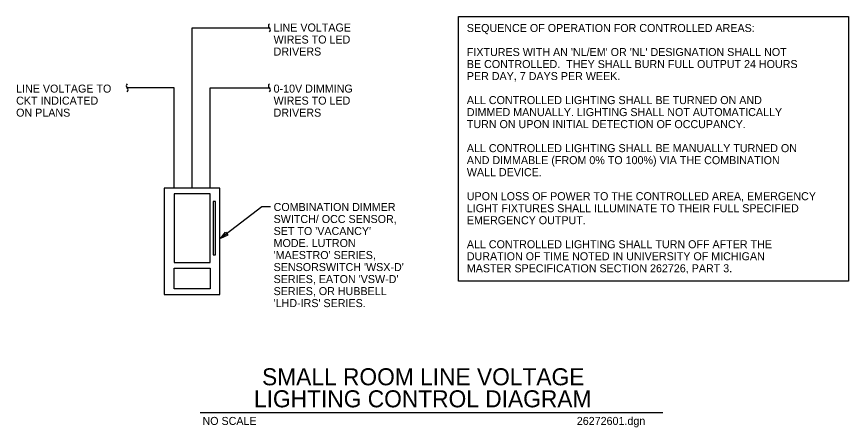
# Model space of a CAD drawing. Extents: x 10026.6 to 10095.9, y 10005.8 to 10040.
import ezdxf

# ---------------------------------------------------------------- set-up
doc = ezdxf.new("R2010")
doc.units = 0
for name, color, linetype in [('G-ANNO-CELL', 7, 'Continuous'), ('G-ANNO-TEXT', 7, 'Continuous'), ('G-DETL-LINE', 7, 'Continuous'), ('Level 3', 7, 'Continuous')]:
    doc.layers.add(name, color=color, linetype=linetype)

msp = doc.modelspace()

# ---------------------------------------------------------------- linework, layer by layer
at = {"layer": 'G-ANNO-CELL'}
msp.add_line((10041.898, 10007.023), (10080.422, 10007.023), dxfattribs=at)
at = {"layer": 'G-ANNO-TEXT'}
for points in [[(10063.404, 10039.974), (10095.865, 10039.974), (10095.865, 10017.948), (10063.404, 10017.948)], [(10044.202, 10021.776), (10043.574, 10021.497), (10043.997, 10022.039)]]:
    msp.add_lwpolyline(points, close=True, dxfattribs=at)
msp.add_lwpolyline([(10047.743, 10024.155), (10047.014, 10024.155), (10043.574, 10021.497)], dxfattribs=at)
at = {"layer": 'G-DETL-LINE'}
for p, q in [((10041.216, 10025.71), (10041.216, 10039.045)), ((10041.216, 10039.045), (10047.649, 10039.045)), ((10039.716, 10034.045), (10035.802, 10034.045)), ((10039.716, 10025.71), (10039.716, 10034.045)), ((10042.716, 10025.71), (10042.716, 10034.045)), ((10042.716, 10034.045), (10047.649, 10034.045))]:
    msp.add_line(p, q, dxfattribs=at)
for points in [[(10043.532, 10025.71), (10038.9, 10025.71), (10038.9, 10016.834), (10043.532, 10016.834)], [(10042.716, 10025.231), (10039.716, 10025.231), (10039.716, 10019.507), (10042.716, 10019.507)], [(10043.168, 10024.577), (10042.959, 10024.577), (10042.959, 10020.161), (10043.168, 10020.161)], [(10042.716, 10017.313), (10039.716, 10017.313), (10039.716, 10019.05), (10042.716, 10019.05)]]:
    msp.add_lwpolyline(points, close=True, dxfattribs=at)
for centre, start, end in [((10047.774, 10039.212), 126.8699, 233.1301), ((10047.524, 10038.879), 306.8699, 53.1301), ((10035.927, 10034.212), 126.8699, 233.1301), ((10047.774, 10034.212), 126.8699, 233.1301), ((10035.677, 10033.879), 306.8699, 53.1301), ((10047.524, 10033.879), 306.8699, 53.1301)]:
    msp.add_arc(centre, 0.208, start, end, dxfattribs=at)

# ---------------------------------------------------------------- texts
at = {"layer": 'G-ANNO-CELL'}
for s, height, p in [('SMALL ROOM LINE VOLTAGE', 1.41667, (10047.039, 10009.289)), ('LIGHTING CONTROL DIAGRAM', 1.41667, (10046.365, 10007.455)), ('NO SCALE', 0.6667, (10042.078, 10005.988))]:
    msp.add_text(s, height=height, dxfattribs=at).set_placement(p)
at = {"layer": 'G-ANNO-TEXT'}
for s, height, p in [('LINE VOLTAGE ', 0.66667, (10048.001, 10038.735)), ('SEQUENCE OF OPERATION FOR CONTROLLED AREAS:', 0.66667, (10064.092, 10038.695)), ('WIRES TO LED ', 0.66667, (10048.001, 10037.735)), ('DRIVERS', 0.6667, (10048.001, 10036.735)), ("FIXTURES WITH AN 'NL/EM' OR 'NL' DESIGNATION SHALL NOT ", 0.66667, (10064.092, 10036.695)), ('BE CONTROLLED.  THEY SHALL BURN FULL OUTPUT 24 HOURS ', 0.66667, (10064.092, 10035.695)), ('PER DAY, 7 DAYS PER WEEK.', 0.66667, (10064.092, 10034.695)), ('LINE VOLTAGE TO ', 0.66667, (10026.559, 10033.65)), ('0-10V DIMMING ', 0.66667, (10048.001, 10033.65)), ('CKT INDICATED ', 0.66667, (10026.559, 10032.65)), ('WIRES TO LED ', 0.66667, (10048.001, 10032.65)), ('ALL CONTROLLED LIGHTING SHALL BE TURNED ON AND ', 0.66667, (10064.092, 10032.695)), ('ON PLANS', 0.6667, (10026.559, 10031.65)), ('DRIVERS', 0.6667, (10048.001, 10031.65)), ('DIMMED MANUALLY. LIGHTING SHALL NOT AUTOMATICALLY ', 0.66667, (10064.092, 10031.695)), ('TURN ON UPON INITIAL DETECTION OF OCCUPANCY.', 0.66667, (10064.092, 10030.695)), ('ALL CONTROLLED LIGHTING SHALL BE MANUALLY TURNED ON ', 0.66667, (10064.092, 10028.695)), ('AND DIMMABLE (FROM 0% TO 100%) VIA THE COMBINATION ', 0.66667, (10064.092, 10027.695)), ('WALL DEVICE.', 0.66667, (10064.092, 10026.695)), ('UPON LOSS OF POWER TO THE CONTROLLED AREA, EMERGENCY ', 0.66667, (10064.092, 10024.695)), ('COMBINATION DIMMER ', 0.66667, (10048.001, 10023.796)), ('LIGHT FIXTURES SHALL ILLUMINATE TO THEIR FULL SPECIFIED ', 0.66667, (10064.092, 10023.695)), ('SWITCH/ OCC SENSOR, ', 0.66667, (10048.001, 10022.796)), ('EMERGENCY OUTPUT.', 0.66667, (10064.092, 10022.695)), ("SET TO 'VACANCY' ", 0.66667, (10048.001, 10021.796)), ('MODE. LUTRON ', 0.66667, (10048.001, 10020.796)), ('ALL CONTROLLED LIGHTING SHALL TURN OFF AFTER THE ', 0.66667, (10064.092, 10020.695)), ("'MAESTRO' SERIES, ", 0.66667, (10048.001, 10019.796)), ('DURATION OF TIME NOTED IN UNIVERSITY OF MICHIGAN ', 0.66667, (10064.092, 10019.695)), ("SENSORSWITCH 'WSX-D' ", 0.66667, (10048.001, 10018.796)), ('MASTER SPECIFICATION SECTION 262726, PART 3.', 0.66667, (10064.092, 10018.695)), ("SERIES, EATON 'VSW-D' ", 0.66667, (10048.001, 10017.796)), ('SERIES, OR HUBBELL ', 0.66667, (10048.001, 10016.796)), ("'LHD-IRS' SERIES.", 0.66667, (10048.001, 10015.796))]:
    msp.add_text(s, height=height, dxfattribs=at).set_placement(p)
at = {"layer": 'Level 3'}
msp.add_text('26272601.dgn', height=0.66667, dxfattribs=at).set_placement((10073.251, 10005.988))

doc.saveas('drawing.dxf')
